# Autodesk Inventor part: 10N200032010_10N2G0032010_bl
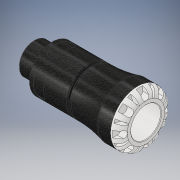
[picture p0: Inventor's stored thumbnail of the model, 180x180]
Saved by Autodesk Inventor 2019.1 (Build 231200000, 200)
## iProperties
Created: 2016-12
Part Number: 10N200032010_10N2G0032010_bl
Material: PVC-Piping
Description: PLASSON MALE ADAPTOR 32X1" SERIES 1
Document SubType Name: Modeling
Designer: KIM
Mass: 61.7504 g
Surface Area: 140.097 cm^2
Volume: 44.1074 cm^3
Density: 1.4 g/cm^3
Appearance: Black Cast
Author: KIM
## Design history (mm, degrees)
derived "10N20.ipt"
feature "Solid1::10N20.ipt" dims "ScaleForDerivedMember" = 10
tag "TaggingFeature1"
body "Solid1"
other parameters: "d1" = 23.1 [user parameter], "d2" = 32 [user parameter], "d4" = 58 [user parameter], "d6" = 55 [user parameter], "d8" = 49.3 [user parameter], "d13" = 7.2 [user parameter], "d14" = 7.2 [user parameter], "d15" = 0 [user parameter], "d17" = 360 deg [user parameter], "d19" = 8 deg [user parameter], "d20" = 0.64 [user parameter], "d21" = 0.64 [user parameter], "d22" = 8 deg [user parameter], "d24" = 0 [user parameter], "d26" = 360 deg [user parameter], "d32" = 0.925 [user parameter], "d33" = 5.8 [user parameter], "d34" = 33.249 [user parameter], "d35" = 4 [user parameter], "d38" = 19 [user parameter], "d39" = 0.99747 [user parameter], "d42" = 11.2 [user parameter], "d43" = 7.36 [user parameter], "d45" = 14.112 [user parameter], "d46" = 0 [user parameter], "d59" = 360 deg [user parameter], "d61" = 9.52 [user parameter], "d62" = 0.64 [user parameter], "d64" = 0 [user parameter], "d65" = 0.58 [user parameter], "d69" = 2 [user parameter], "d70" = 1.8 [user parameter], "d71" = 3 [user parameter], "d73" = 1 [user parameter], "d_" = 32 [user parameter], "E_" = 58 [user parameter], "l_" = 55 [user parameter], "R_" = 33.249 [user parameter], "l_2" = 19 [user parameter], "d9" = 9 [user parameter], "d11" = 58 [user parameter]
